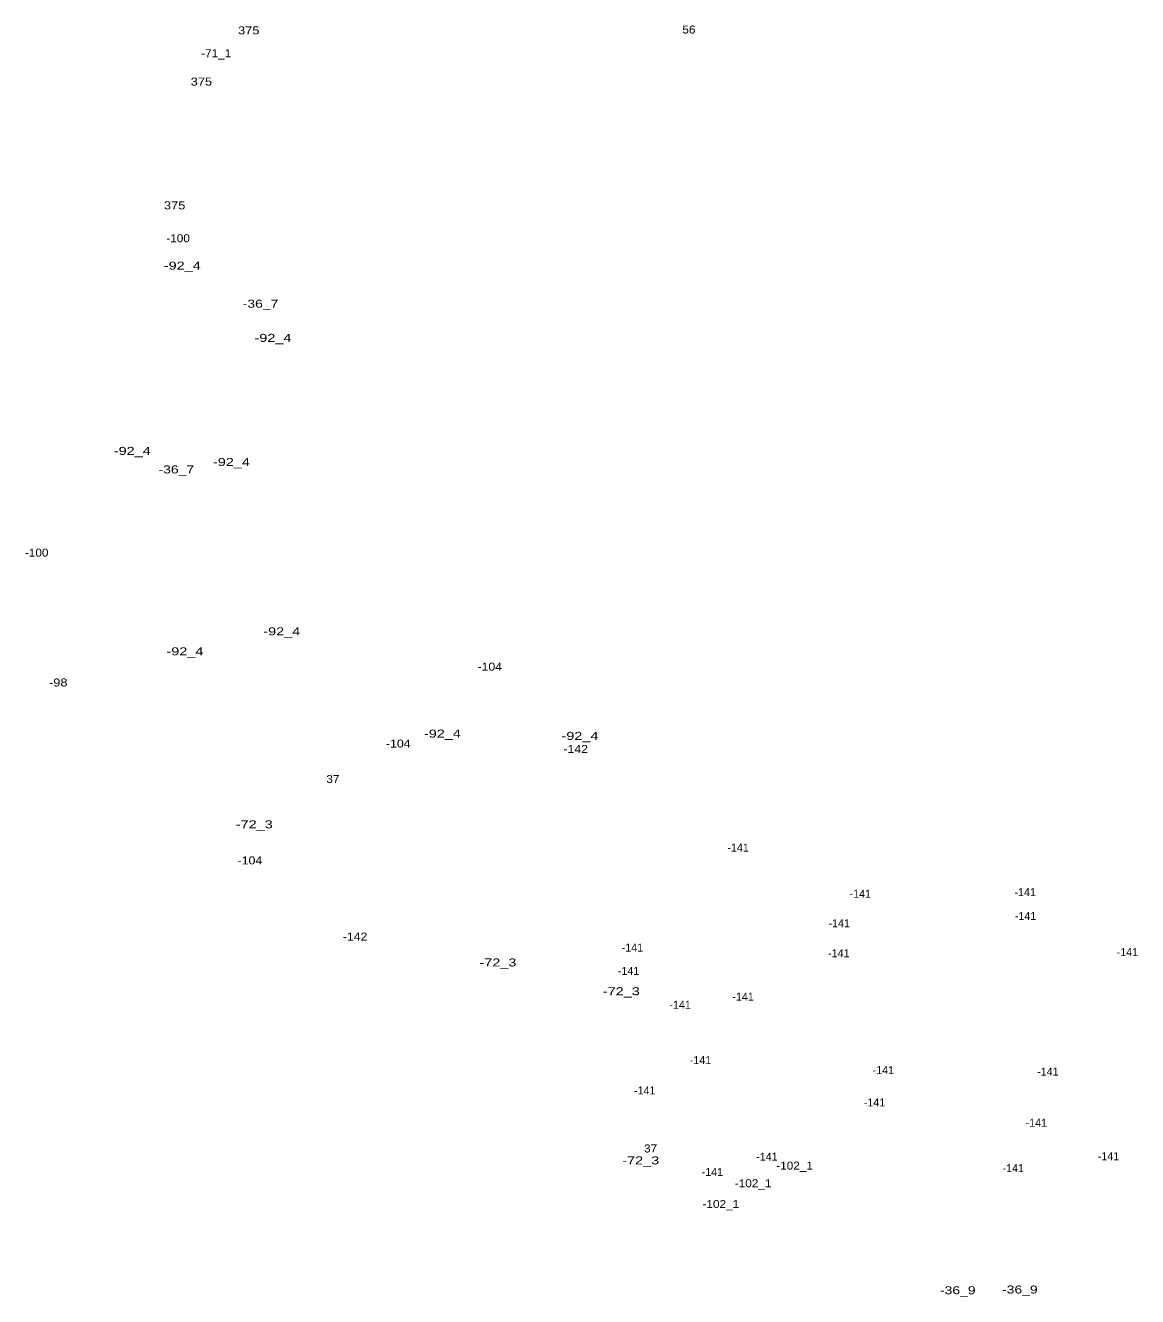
# Model space of a CAD drawing. Extents: x -658110 to -655750, y -1000429 to -997657.
# Drawn here: x -656306 to -655750, y -999753 to -999118 of the extents above; entities that cross this region are included whole.
import ezdxf
from ezdxf.enums import TextEntityAlignment as Align

# ---------------------------------------------------------------- set-up
doc = ezdxf.new("R2010")
doc.units = 0
doc.header["$LTSCALE"] = 1.6
doc.layers.add('24', color=7, linetype='Continuous')

msp = doc.modelspace()

# ---------------------------------------------------------------- texts
at = {"layer": '24'}
for s, width, p in [('375', 1.2, (-656194.54, -999122.46)), ('56', 1.1, (-655974.62, -999122.04)), ('-71_1', 1.1, (-656210.811, -999133.87)), ('375', 1.2, (-656218.19, -999148.06)), ('375', 1.2, (-656231.57, -999209.92)), ('-100', 1.1, (-656229.831, -999226.34)), ('-92_4', 1.35, (-656227.77, -999240.03)), ('-36_7', 1.3, (-656188.66, -999259.07)), ('-92_4', 1.35, (-656182.46, -999276.14)), ('-92_4', 1.35, (-656252.73, -999332.61)), ('-36_7', 1.3, (-656230.731, -999341.88)), ('-92_4', 1.35, (-656203.2, -999338.18)), ('-100', 1.1, (-656300.49, -999383.46)), ('-92_4', 1.35, (-656178.04, -999422.8)), ('-92_4', 1.35, (-656226.43, -999432.79)), ('-104', 1.15, (-656074.14, -999440.45)), ('-98', 1.2, (-656289.73, -999448.35)), ('-92_4', 1.35, (-656097.78, -999473.89)), ('-92_4', 1.35, (-656029.04, -999475.05)), ('-104', 1.15, (-656119.84, -999478.87)), ('-142', 1.15, (-656031.18, -999481.6)), ('37', 1.1, (-656152.5, -999496.59)), ('-72_3', 1.35, (-656191.79, -999519.25)), ('-104', 1.15, (-656193.95, -999537.26)), ('-142', 1.15, (-656141.39, -999575.33)), ('-72_3', 1.35, (-656070.04, -999588.29)), ('-72_3', 1.35, (-656008.39, -999602.65)), ('37', 1.1, (-655993.78, -999681.25)), ('-72_3', 1.35, (-655998.7, -999687.21)), ('-102_1', 1.1, (-655921.81, -999689.79)), ('-102_1', 1.1, (-655942.55, -999698.63)), ('-102_1', 1.1, (-655958.68, -999709)), ('-36_9', 1.3, (-655840.28, -999752.1)), ('-36_9', 1.3, (-655809.26, -999751.72))]:
    msp.add_text(s, height=4, dxfattribs=dict(at, width=width)).set_placement(p, align=Align.CENTER)
for p in [(-655950.04, -999530.87), (-655888.98, -999553.92), (-655806.61, -999553.14), (-655899.54, -999568.7), (-655806.42, -999565.05), (-656002.84, -999580.81), (-655899.74, -999583.68), (-655755.54, -999583.1), (-656004.76, -999592.53), (-655947.55, -999605.38), (-655979.03, -999609.42), (-655968.86, -999637.08), (-655877.46, -999642.07), (-655795.28, -999642.84), (-655996.7, -999652.26), (-655881.88, -999658.21), (-655801.04, -999668.39), (-655935.64, -999685.3), (-655764.95, -999685.1), (-655812.56, -999691.05), (-655962.9, -999692.99)]:
    msp.add_text('-141', height=4, dxfattribs=at).set_placement(p, align=Align.CENTER)

doc.saveas('drawing.dxf')
